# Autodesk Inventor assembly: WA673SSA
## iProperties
Category: PARTsolutions
Created: 2011-07
Part Number: WA673SSA
Catalog Web Link: www.cadenas.de
Description: With double shield ZZ -
Document SubType Name: Assembly
Designer: PARTsolutions
NB: WA673SSA
NN: With double shield ZZ
NBSYN: $ORDER.
LINA: WA673SSA
PSOL_MULTISOLIDPART: 0.0
SD: 3.0
D: 6
B: 2.0
B1: 2.5
D1: 7.2
D2: 7.2
C1: 0.6
C2: 0.6
R: 0.08
ORDER: WA673SSA
CR: 242
COR: 94
CRF: 25
CORF: 9,5
LSG: 60 000
LSO: 71 000
MASS: 0.20
ORDER1: 673
WSS: WA673SSA
WDS: SSA
UTWF: FL673
FORSS: FLWA673SA
FORDS: SSA
DA1: 3,6
DA2: 4,1
DA: 5,4
RAS: 0,08
MASS1: 0.26
VERS: 3
X: 1.500
N: 9
O: 14.130
RB: 0.444
PPATH: mss_asmtpl.prj
KT: DUMMY
CreationOption_UseAsmMates: 0
SUPPLIER: NTN
ARTICLENO: WA673SSA
BOMINFO: WA673SSA
CREATOR: CADENAS GmbH
PSOL_IDENT_0: {\\10.0.0.251\ps_data\23d-libs\ntn\ball_roller_bearings\miniature_extra_small_bb\metric_system_sizes
PSOL_IDENT_1: \mss_zz_asmtab.prj},181 {VTYP=3D},{STYP=ASSTAB},{NB=WA673SSA},{LINA=WA673SSA},{NN=With double shield
PSOL_IDENT_2: ZZ},{DATE=11.12.2007 08:48:24},{GEOMDATE=17.04.2007},{VERSION=},{LINEID=12590},{LINESUBID=-1},{WBVA
PSOL_IDENT_3: R=}  {NB=WA673SSA},{LINA=WA673SSA},{KT=DUMMY},{IDNR=},{SD=3.0},{D=6},{B=2.0},{B1=2.5},{D1=7.2},{D2=7
PSOL_IDENT_4: .2},{C1=0.6},{C2=0.6},{R=0.08},{ORDER=WA673SSA},{CR=242},{COR=94},{CRF=25},{CORF=9,5},{LSG=60 000},{
PSOL_IDENT_5: LSO=71 000},{MASS=0.20},{ORDER1=673},{WSS=WA673SSA},{WDS=SSA},{UTWF=FL673},{FORSS=FLWA673SA},{FORDS=
PSOL_IDENT_6: SSA},{DA1=3,6},{DA2=4,1},{DA=5,4},{RAS=0,08},{MASS1=0.26},{VERS=3},{X=1.5},{N=9},{O=14.13},{RB=0.444
PSOL_IDENT_7: },{PPATH=mss_asmtpl.prj}
Title: WA673SSA
Author: Cadenas PARTsolutions
